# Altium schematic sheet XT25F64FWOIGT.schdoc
size 127 x 101 mm
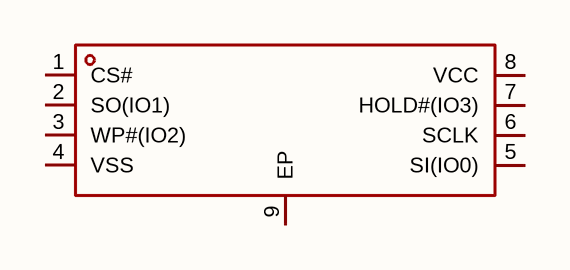
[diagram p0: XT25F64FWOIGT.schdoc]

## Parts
U?  xt25f64fwoigt  [WSON-8_L6.0-W5.0-P1.27-BL-EP]  (value not drawn)

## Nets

Not connected (* = marked no-connect by the designer): U? 1(CS#) 2(SO(IO1)) 3(WP#(IO2)) 4(VSS) 5(SI(IO0)) 6(SCLK) 7(HOLD#(IO3)) 8(VCC) 9(EP)

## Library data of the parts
U? = xt25f64fwoigt: 接口类型:SPI;存储容量:64Mbit;时钟频率(fc):133MHz;; Manufacturer: XTX(芯天下); AddInBom: yes; ModelId: 72347fabc1e24788a361efd6527ab939; ModelName: WSON-8_L6.0-W5.0-H0.7-P1.27; ModelTransform: 237.007,196.85,0,90,0,0,0,0,0; Interface: SPI; Memory Size: 64Mbit; Clock Frequency: 133MHz; Voltage - Supply: 2.7V~3.6V; Standby Supply Current: 0.3uA; Program / Erase Cycles: 100000次; Page Programming Time (Tpp): 400us; Data Retention - TDR (Year): 20年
